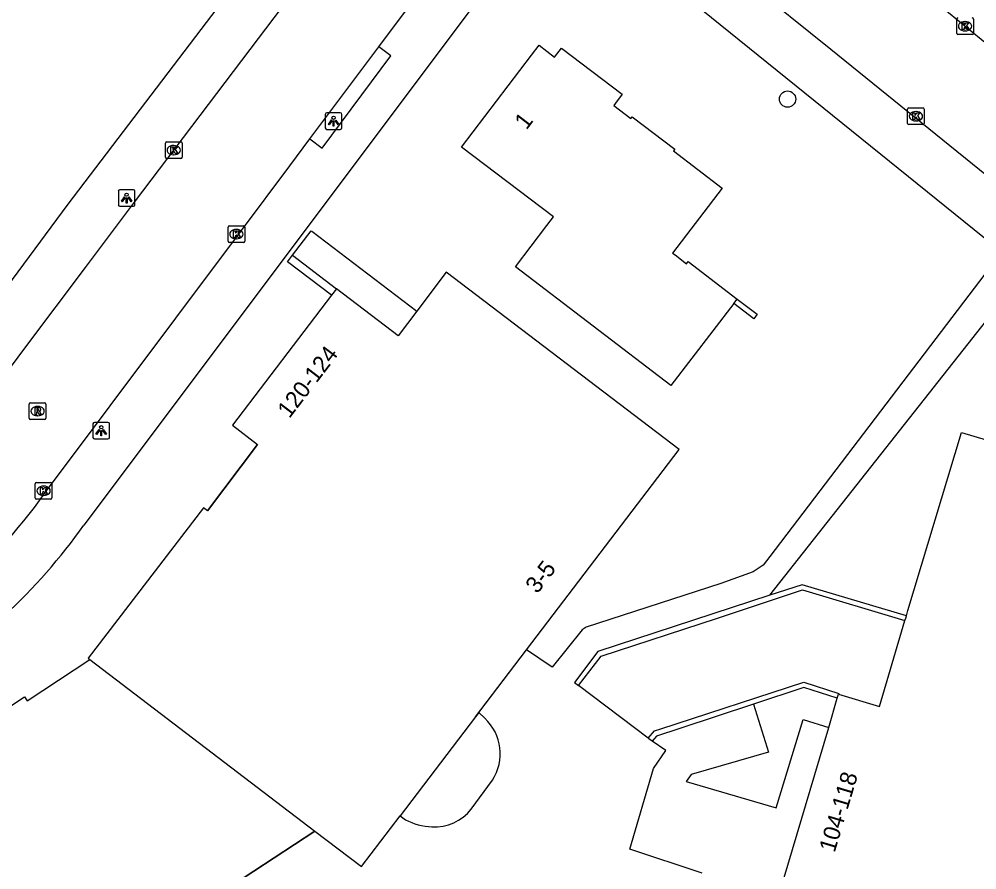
# Model space of a CAD drawing. Extents: x 161141 to 161601, y 381708 to 382245.
# Drawn here: x 161351.2 to 161408.7, y 381859.9 to 381911 of the extents above; entities that cross this region are included whole.
import ezdxf

# ---------------------------------------------------------------- set-up
doc = ezdxf.new("R2010")
doc.units = 0
for name, color, linetype in [('IMGEO_Boom', 7, 'Continuous'), ('IMGEO_Hek', 7, 'Continuous'), ('IMGEO_Kolk', 7, 'Continuous'), ('IMGEO_Lichtpunt', 7, 'Continuous'), ('IMGEO_Muur', 7, 'Continuous'), ('IMGEO_Pand', 7, 'Continuous'), ('IMGEO_Pand_nummerreeks', 7, 'Continuous'), ('IMGEO_Rijbaan_lokaal_open', 7, 'Continuous'), ('IMGEO_Rioolput', 7, 'Continuous'), ('IMGEO_Voetpad_gesloten', 7, 'Continuous'), ('IMGEO_Voetpad_op_trap', 7, 'Continuous'), ('IMGEO_Voetpad_open', 7, 'Continuous')]:
    doc.layers.add(name, color=color, linetype=linetype)

msp = doc.modelspace()

# ---------------------------------------------------------------- linework, layer by layer
at = {"layer": 'IMGEO_Boom'}
msp.add_circle((161397.349, 381906.221), 0.489, dxfattribs=at)
at = {"layer": 'IMGEO_Hek'}
for points in [[(161362.5, 381881.493), (161365.51, 381885.478)], [(161378.602, 381869.107), (161381.677, 381873.144)], [(161351.666, 381870.071), (161355.437, 381872.558)], [(161360.471, 381856.669), (161368.964, 381862.254)]]:
    msp.add_lwpolyline(points, dxfattribs=at)
at = {"layer": 'IMGEO_Kolk'}
for p, q in [((161407.513, 381910.173), (161407.513, 381911.025)), ((161408.001, 381910.879), (161408.026, 381910.879)), ((161408.514, 381911.025), (161408.514, 381910.173)), ((161408.024, 381910.319), (161407.999, 381910.319)), ((161408.44, 381910.099), (161407.588, 381910.099)), ((161404.558, 381904.763), (161404.558, 381905.615)), ((161404.633, 381905.689), (161405.485, 381905.689)), ((161405.559, 381905.615), (161405.559, 381904.763)), ((161405.046, 381905.469), (161405.071, 381905.469)), ((161405.485, 381904.689), (161404.633, 381904.689)), ((161405.069, 381904.909), (161405.044, 381904.909)), ((161359.98, 381902.729), (161359.98, 381903.581)), ((161360.055, 381903.655), (161360.907, 381903.655)), ((161360.468, 381903.435), (161360.493, 381903.435)), ((161360.981, 381903.581), (161360.981, 381902.729)), ((161360.491, 381902.875), (161360.466, 381902.875)), ((161360.907, 381902.655), (161360.055, 381902.655)), ((161363.743, 381897.685), (161363.743, 381898.537)), ((161363.818, 381898.611), (161364.67, 381898.611)), ((161364.231, 381898.391), (161364.256, 381898.391)), ((161364.744, 381898.537), (161364.744, 381897.685)), ((161364.67, 381897.611), (161363.818, 381897.611)), ((161364.254, 381897.831), (161364.229, 381897.831)), ((161352.235, 381883.192), (161353.087, 381883.192)), ((161352.16, 381882.266), (161352.16, 381883.118)), ((161352.648, 381882.972), (161352.673, 381882.972)), ((161353.161, 381883.118), (161353.161, 381882.266)), ((161353.087, 381882.192), (161352.235, 381882.192)), ((161352.671, 381882.412), (161352.646, 381882.412))]:
    msp.add_line(p, q, dxfattribs=at)
for points in [[(161407.513, 381910.173), (161407.513, 381911.025)], [(161407.834, 381910.799), (161407.957, 381910.799), (161407.957, 381910.648), (161408.087, 381910.799), (161408.251, 381910.799), (161408.105, 381910.648), (161408.258, 381910.399), (161408.106, 381910.399), (161408.021, 381910.563), (161407.957, 381910.496), (161407.957, 381910.399), (161407.834, 381910.399), (161407.834, 381910.799)], [(161408.514, 381911.025), (161408.514, 381910.173)], [(161408.44, 381910.099), (161407.588, 381910.099)], [(161404.558, 381904.763), (161404.558, 381905.615)], [(161404.633, 381905.689), (161405.485, 381905.689)], [(161405.559, 381905.615), (161405.559, 381904.763)], [(161404.879, 381905.389), (161405.002, 381905.389), (161405.002, 381905.238), (161405.132, 381905.389), (161405.296, 381905.389), (161405.15, 381905.238), (161405.303, 381904.989), (161405.151, 381904.989), (161405.066, 381905.153), (161405.002, 381905.086), (161405.002, 381904.989), (161404.879, 381904.989), (161404.879, 381905.389)], [(161405.485, 381904.689), (161404.633, 381904.689)], [(161359.98, 381902.729), (161359.98, 381903.581)], [(161360.055, 381903.655), (161360.907, 381903.655)], [(161360.301, 381903.355), (161360.424, 381903.355), (161360.424, 381903.204), (161360.554, 381903.355), (161360.718, 381903.355), (161360.572, 381903.204), (161360.725, 381902.955), (161360.573, 381902.955), (161360.488, 381903.119), (161360.424, 381903.052), (161360.424, 381902.955), (161360.301, 381902.955), (161360.301, 381903.355)], [(161360.981, 381903.581), (161360.981, 381902.729)], [(161360.907, 381902.655), (161360.055, 381902.655)], [(161363.743, 381897.685), (161363.743, 381898.537)], [(161363.818, 381898.611), (161364.67, 381898.611)], [(161364.064, 381898.311), (161364.187, 381898.311), (161364.187, 381898.16), (161364.317, 381898.311), (161364.481, 381898.311), (161364.335, 381898.16), (161364.488, 381897.911), (161364.336, 381897.911), (161364.251, 381898.075), (161364.187, 381898.008), (161364.187, 381897.911), (161364.064, 381897.911), (161364.064, 381898.311)], [(161364.744, 381898.537), (161364.744, 381897.685)], [(161364.67, 381897.611), (161363.818, 381897.611)], [(161352.235, 381883.192), (161353.087, 381883.192)], [(161352.16, 381882.266), (161352.16, 381883.118)], [(161352.481, 381882.892), (161352.604, 381882.892), (161352.604, 381882.741), (161352.734, 381882.892), (161352.898, 381882.892), (161352.752, 381882.741), (161352.905, 381882.492), (161352.753, 381882.492), (161352.668, 381882.656), (161352.604, 381882.589), (161352.604, 381882.492), (161352.481, 381882.492), (161352.481, 381882.892)], [(161353.161, 381883.118), (161353.161, 381882.266)], [(161353.087, 381882.192), (161352.235, 381882.192)]]:
    msp.add_lwpolyline(points, dxfattribs=at)
for centre, start, end in [((161407.59, 381911.023), 91.55205, 178.44795), ((161407.59, 381911.023), 91.55205, 178.44795), ((161408.438, 381911.023), 1.55205, 88.44795), ((161408.438, 381911.023), 1.55205, 88.44795), ((161407.59, 381910.175), 181.55205, 268.44795), ((161407.59, 381910.175), 181.55205, 268.44795), ((161408.438, 381910.175), 271.55205, 358.44795), ((161408.438, 381910.175), 271.55205, 358.44795), ((161404.635, 381905.613), 91.55205, 178.44795), ((161404.635, 381905.613), 91.55205, 178.44795), ((161405.483, 381905.613), 1.55205, 88.44795), ((161405.483, 381905.613), 1.55205, 88.44795), ((161404.635, 381904.765), 181.55205, 268.44795), ((161404.635, 381904.765), 181.55205, 268.44795), ((161405.483, 381904.765), 271.55205, 358.44795), ((161405.483, 381904.765), 271.55205, 358.44795), ((161360.057, 381903.579), 91.55205, 178.44795), ((161360.057, 381903.579), 91.55205, 178.44795), ((161360.905, 381903.579), 1.55205, 88.44795), ((161360.905, 381903.579), 1.55205, 88.44795), ((161360.057, 381902.731), 181.55205, 268.44795), ((161360.057, 381902.731), 181.55205, 268.44795), ((161360.905, 381902.731), 271.55205, 358.44795), ((161360.905, 381902.731), 271.55205, 358.44795), ((161363.82, 381898.535), 91.55205, 178.44795), ((161363.82, 381898.535), 91.55205, 178.44795), ((161364.668, 381898.535), 1.55205, 88.44795), ((161364.668, 381898.535), 1.55205, 88.44795), ((161363.82, 381897.687), 181.55205, 268.44795), ((161363.82, 381897.687), 181.55205, 268.44795), ((161364.668, 381897.687), 271.55205, 358.44795), ((161364.668, 381897.687), 271.55205, 358.44795), ((161352.237, 381883.116), 91.55205, 178.44795), ((161352.237, 381883.116), 91.55205, 178.44795), ((161353.085, 381883.116), 1.55205, 88.44795), ((161353.085, 381883.116), 1.55205, 88.44795), ((161352.237, 381882.268), 181.55205, 268.44795), ((161352.237, 381882.268), 181.55205, 268.44795), ((161353.085, 381882.268), 271.55205, 358.44795), ((161353.085, 381882.268), 271.55205, 358.44795)]:
    msp.add_arc(centre, 0.0765, start, end, dxfattribs=at)
for centre, major_axis, ratio, start_param, end_param in [((161408, 381910.599), (-0.387, 0.002), 0.722429, 4.712389, 7.853982), ((161408.025, 381910.599), (-0.39, 0.002), 0.717154, 1.570796, 4.712389), ((161405.045, 381905.189), (-0.387, 0.002), 0.722429, 4.712389, 7.853982), ((161405.07, 381905.189), (-0.39, 0.002), 0.717154, 1.570796, 4.712389), ((161360.467, 381903.155), (-0.387, 0.002), 0.722429, 4.712389, 7.853982), ((161360.492, 381903.155), (-0.39, 0.002), 0.717154, 1.570796, 4.712389), ((161364.23, 381898.111), (-0.387, 0.002), 0.722429, 4.712389, 7.853982), ((161364.255, 381898.111), (-0.39, 0.002), 0.717154, 1.570796, 4.712389), ((161352.647, 381882.692), (-0.387, 0.002), 0.722429, 4.712389, 7.853982), ((161352.672, 381882.692), (-0.39, 0.002), 0.717154, 1.570796, 4.712389)]:
    msp.add_ellipse(centre, major_axis=major_axis, ratio=ratio, start_param=start_param, end_param=end_param, dxfattribs=at)
at = {"layer": 'IMGEO_Lichtpunt'}
for p, q in [((161369.583, 381905.303), (161369.583, 381904.496)), ((161369.583, 381905.303), (161369.583, 381904.496)), ((161370.485, 381905.398), (161369.677, 381905.398)), ((161370.485, 381905.398), (161369.677, 381905.398)), ((161370.579, 381904.496), (161370.579, 381905.303)), ((161370.579, 381904.496), (161370.579, 381905.303)), ((161369.677, 381904.402), (161370.485, 381904.402)), ((161369.677, 381904.402), (161370.485, 381904.402)), ((161357.152, 381900.683), (161357.152, 381899.876)), ((161357.152, 381900.683), (161357.152, 381899.876)), ((161358.054, 381900.778), (161357.246, 381900.778)), ((161358.054, 381900.778), (161357.246, 381900.778)), ((161358.148, 381899.876), (161358.148, 381900.683)), ((161358.148, 381899.876), (161358.148, 381900.683)), ((161357.246, 381899.782), (161358.054, 381899.782)), ((161357.246, 381899.782), (161358.054, 381899.782)), ((161355.623, 381886.707), (161355.623, 381885.9)), ((161355.623, 381886.707), (161355.623, 381885.9)), ((161356.525, 381886.802), (161355.717, 381886.802)), ((161356.525, 381886.802), (161355.717, 381886.802)), ((161356.619, 381885.9), (161356.619, 381886.707)), ((161356.619, 381885.9), (161356.619, 381886.707)), ((161355.717, 381885.806), (161356.525, 381885.806)), ((161355.717, 381885.806), (161356.525, 381885.806))]:
    msp.add_line(p, q, dxfattribs=at)
for points in [[(161369.957, 381904.967), (161369.996, 381904.939), (161369.808, 381904.677), (161369.77, 381904.704), (161369.957, 381904.967)], [(161370.059, 381904.919), (161370.106, 381904.919), (161370.106, 381904.597), (161370.059, 381904.597), (161370.059, 381904.919)], [(161370.169, 381904.939), (161370.207, 381904.966), (161370.394, 381904.704), (161370.355, 381904.676), (161370.169, 381904.939)], [(161357.526, 381900.347), (161357.565, 381900.319), (161357.377, 381900.057), (161357.339, 381900.084), (161357.526, 381900.347)], [(161357.628, 381900.299), (161357.675, 381900.299), (161357.675, 381899.977), (161357.628, 381899.977), (161357.628, 381900.299)], [(161357.738, 381900.319), (161357.776, 381900.346), (161357.963, 381900.084), (161357.924, 381900.056), (161357.738, 381900.319)], [(161355.997, 381886.371), (161356.036, 381886.343), (161355.848, 381886.081), (161355.81, 381886.108), (161355.997, 381886.371)], [(161356.099, 381886.323), (161356.146, 381886.323), (161356.146, 381886.001), (161356.099, 381886.001), (161356.099, 381886.323)], [(161356.209, 381886.343), (161356.247, 381886.37), (161356.434, 381886.108), (161356.395, 381886.08), (161356.209, 381886.343)]]:
    msp.add_lwpolyline(points, dxfattribs=at)
for centre in [(161370.082, 381905.101), (161357.651, 381900.481), (161356.122, 381886.505)]:
    msp.add_circle(centre, 0.0994, dxfattribs=at)
for centre, start, end in [((161369.677, 381905.303), 90, 180), ((161369.677, 381905.303), 90, 180), ((161370.485, 381905.303), 0, 90), ((161370.485, 381905.303), 0, 90), ((161369.677, 381904.496), 180, 270), ((161369.677, 381904.496), 180, 270), ((161370.485, 381904.496), 270, 0), ((161370.485, 381904.496), 270, 360), ((161357.246, 381900.683), 90, 180), ((161357.246, 381900.683), 90, 180), ((161358.054, 381900.683), 0, 90), ((161358.054, 381900.683), 0, 90), ((161357.246, 381899.876), 180, 270), ((161357.246, 381899.876), 180, 270), ((161358.054, 381899.876), 270, 0), ((161358.054, 381899.876), 270, 360), ((161355.717, 381886.707), 90, 180), ((161355.717, 381886.707), 90, 180), ((161356.525, 381886.707), 0, 90), ((161356.525, 381886.707), 0, 90), ((161355.717, 381885.9), 180, 270), ((161355.717, 381885.9), 180, 270), ((161356.525, 381885.9), 270, 0), ((161356.525, 381885.9), 270, 360)]:
    msp.add_arc(centre, 0.0946, start, end, dxfattribs=at)
at = {"layer": 'IMGEO_Muur'}
for points in [[(161369.955, 381894.435), (161367.312, 381896.447), (161367.614, 381896.841)], [(161367.614, 381896.841), (161370.262, 381894.819)], [(161394.333, 381894.213), (161395.529, 381893.303), (161395.317, 381893.025), (161394.124, 381893.943)], [(161404.489, 381875.181), (161398.229, 381877.051), (161396.286, 381876.416)], [(161396.286, 381876.416), (161385.946, 381873.035), (161384.544, 381871.18), (161384.784, 381871)], [(161384.784, 381871), (161386.159, 381872.748), (161393.152, 381875.047), (161398.239, 381876.735), (161404.403, 381874.894)], [(161388.983, 381867.825), (161389.367, 381868.28), (161389.733, 381868.393), (161398.335, 381871.191), (161400.422, 381870.513), (161400.411, 381870.476)], [(161400.337, 381870.225), (161398.337, 381870.875), (161395.311, 381869.871)], [(161395.311, 381869.871), (161390.886, 381868.403), (161389.475, 381867.942), (161389.223, 381867.644)], [(161389.223, 381867.644), (161389.02, 381867.798), (161388.983, 381867.825)]]:
    msp.add_lwpolyline(points, dxfattribs=at)
at = {"layer": 'IMGEO_Pand'}
for points in [[(161394.124, 381893.943), (161390.337, 381889.021), (161381.005, 381896.145), (161382.897, 381898.632), (161383.285, 381899.142), (161377.771, 381903.34), (161381.969, 381908.853), (161382.429, 381909.459), (161383.354, 381908.75), (161383.765, 381909.292), (161387.42, 381906.518), (161387.018, 381905.98), (161386.918, 381905.847), (161387.94, 381905.066), (161388.016, 381905.165), (161390.578, 381903.207), (161390.502, 381903.108), (161393.417, 381900.88), (161390.444, 381896.971), (161390.591, 381896.859), (161391.284, 381896.332), (161391.385, 381896.466), (161394.333, 381894.213)], [(161381.677, 381873.144), (161390.838, 381885.171), (161376.851, 381895.819), (161375.084, 381893.489)], [(161370.262, 381894.819), (161369.955, 381894.435)], [(161375.084, 381893.489), (161373.955, 381892.001), (161370.262, 381894.819)], [(161369.955, 381894.435), (161364, 381886.63), (161365.51, 381885.478), (161362.5, 381881.493), (161362.266, 381881.673), (161355.333, 381872.637), (161355.437, 381872.558)], [(161394.124, 381893.943), (161394.333, 381894.213)], [(161404.489, 381875.181), (161404.584, 381875.499), (161407.805, 381886.188), (161423.433, 381881.545), (161420.059, 381870.284)], [(161404.403, 381874.894), (161404.449, 381875.049), (161404.489, 381875.181)], [(161400.411, 381870.476), (161402.871, 381869.734), (161404.403, 381874.894)], [(161378.802, 381869.369), (161381.677, 381873.144)], [(161345.758, 381855.638), (161342.849, 381853.685), (161337.847, 381861.294), (161342.013, 381864.045), (161351.507, 381870.313), (161351.666, 381870.071), (161355.437, 381872.558)], [(161355.437, 381872.558), (161368.964, 381862.254)], [(161399.821, 381868.48), (161400.337, 381870.225)], [(161400.337, 381870.225), (161400.411, 381870.476)], [(161378.802, 381869.369), (161378.602, 381869.107), (161374.079, 381863.168)], [(161396.815, 381858.319), (161399.821, 381868.48)], [(161368.964, 381862.254), (161371.759, 381860.122), (161374.079, 381863.168)], [(161368.964, 381862.254), (161360.411, 381856.63)]]:
    msp.add_lwpolyline(points, dxfattribs=at)
at = {"layer": 'IMGEO_Rijbaan_lokaal_open'}
for points in [[(161430.53, 381892.26), (161428.93, 381893.541), (161416.582, 381903.762), (161409.42, 381909.443), (161405.146, 381912.95), (161401.483, 381915.955), (161397.742, 381918.904), (161394.58, 381921.397), (161388.533, 381926.301), (161384.971, 381929.006), (161381.728, 381931.469), (161381.315, 381931.756), (161376.383, 381935.18), (161370.251, 381939.135), (161367.432, 381940.939), (161364.318, 381942.933), (161361.946, 381944.451), (161354.44, 381949.434), (161345.5, 381955.194), (161345.132, 381955.433), (161341.968, 381957.49), (161334.965, 381962.043), (161325.373, 381968.263), (161318.237, 381972.89)], [(161347.78, 381886.211), (161351.589, 381891.33), (161355.178, 381896.112), (161357.581, 381899.312), (161358.116, 381900.025), (161368.51, 381913.776), (161373.481, 381920.434), (161374.759, 381922.138), (161375.72, 381923.419)], [(161426.69, 381887.564), (161425.057, 381888.885), (161404.152, 381905.797), (161399.947, 381909.192), (161394.957, 381913.221), (161391.403, 381916.091), (161386.448, 381920.091)], [(161372.8, 381909.362), (161380.355, 381919.457)], [(161368.658, 381903.827), (161372.8, 381909.362)], [(161352.722, 381882.533), (161364.546, 381898.333), (161367.452, 381902.216), (161368.658, 381903.827)], [(161410.212, 381897.05), (161396.293, 381878.738), (161395.877, 381878.224), (161395.275, 381877.818), (161393.345, 381877.126), (161385.244, 381874.499), (161385.019, 381874.335), (161383.219, 381872.094), (161381.677, 381873.144)], [(161396.286, 381876.416), (161411.648, 381895.891)], [(161388.983, 381867.825), (161384.784, 381871)], [(161379.167, 381869.023), (161378.802, 381869.369)], [(161392.214, 381859.719), (161387.882, 381861.165), (161389.294, 381866.012), (161390.047, 381867.09), (161389.223, 381867.644)], [(161378.344, 381863.568), (161379.62, 381865.312)], [(161374.079, 381863.168), (161374.394, 381862.928)]]:
    msp.add_lwpolyline(points, dxfattribs=at)
for centre, radius, start, end in [((161325.528, 381901.818), 33.338, 296.19299, 324.65779), ((161377.177, 381866.897), 2.912, 327.02435, 46.89492), ((161376.187, 381865.229), 2.722, 265.88663, 322.39046), ((161376.08, 381866.145), 3.632, 242.34105, 268.60995)]:
    msp.add_arc(centre, radius, start, end, dxfattribs=at)
at = {"layer": 'IMGEO_Rioolput'}
for p, q in [((161351.799, 381887.053), (161351.799, 381887.905)), ((161351.874, 381887.979), (161352.726, 381887.979)), ((161352.8, 381887.905), (161352.8, 381887.053)), ((161352.31, 381887.199), (161352.285, 381887.199)), ((161352.287, 381887.759), (161352.312, 381887.759)), ((161352.726, 381886.979), (161351.874, 381886.979))]:
    msp.add_line(p, q, dxfattribs=at)
for points in [[(161351.799, 381887.053), (161351.799, 381887.905)], [(161351.874, 381887.979), (161352.726, 381887.979)], [(161352.8, 381887.905), (161352.8, 381887.053)], [(161352.388, 381887.677), (161352.136, 381887.679), (161352.136, 381887.279)], [(161352.136, 381887.279), (161352.26, 381887.279), (161352.26, 381887.441), (161352.271, 381887.441)], [(161352.314, 381887.598), (161352.26, 381887.598), (161352.26, 381887.517)], [(161352.26, 381887.517), (161352.312, 381887.517)], [(161352.318, 381887.412), (161352.389, 381887.279), (161352.529, 381887.279), (161352.464, 381887.405)], [(161352.726, 381886.979), (161351.874, 381886.979)]]:
    msp.add_lwpolyline(points, dxfattribs=at)
for centre, radius, start, end in [((161351.876, 381887.903), 0.0765, 91.55205, 178.44795), ((161351.876, 381887.903), 0.0765, 91.55205, 178.44795), ((161352.724, 381887.903), 0.0765, 1.55205, 88.44795), ((161352.724, 381887.903), 0.0765, 1.55205, 88.44795), ((161352.27, 381887.388), 0.0533, 26.02933, 88.69889), ((161352.296, 381887.706), 0.19, 274.7715, 282.96867), ((161352.32, 381887.502), 0.0964, 77.00612, 93.18647), ((161352.334, 381887.559), 0.0378, 276.66336, 79.67722), ((161352.387, 381887.567), 0.109, 350.36119, 89.41601), ((161352.385, 381887.567), 0.112, 277.58423, 350.98172), ((161352.369, 381887.352), 0.108, 29.51342, 73.79051), ((161351.876, 381887.055), 0.0765, 181.55205, 268.44795), ((161351.876, 381887.055), 0.0765, 181.55205, 268.44795), ((161352.724, 381887.055), 0.0765, 271.55205, 358.44795), ((161352.724, 381887.055), 0.0765, 271.55205, 358.44795)]:
    msp.add_arc(centre, radius, start, end, dxfattribs=at)
for centre, major_axis, ratio, start_param, end_param in [((161352.286, 381887.479), (-0.387, 0.002), 0.722429, 4.712389, 7.853982), ((161352.311, 381887.479), (-0.39, 0.002), 0.717154, 1.570796, 4.712389)]:
    msp.add_ellipse(centre, major_axis=major_axis, ratio=ratio, start_param=start_param, end_param=end_param, dxfattribs=at)
at = {"layer": 'IMGEO_Voetpad_gesloten'}
msp.add_lwpolyline([(161395.311, 381869.871), (161396.198, 381866.981), (161391.555, 381865.65), (161391.264, 381865.226), (161396.671, 381863.647), (161398.279, 381868.954), (161399.821, 381868.48)], dxfattribs=at)
at = {"layer": 'IMGEO_Voetpad_op_trap'}
msp.add_lwpolyline([(161367.614, 381896.841), (161368.743, 381898.317), (161368.776, 381898.292), (161375.084, 381893.489)], dxfattribs=at)
at = {"layer": 'IMGEO_Voetpad_open'}
for points in [[(161342.481, 381884.773), (161344.76, 381887.264), (161354.145, 381899.917), (161371.073, 381922.177), (161372.043, 381923.95)], [(161382.438, 381917.119), (161355.077, 381880.626)], [(161384.753, 381917.612), (161384.887, 381917.504), (161410.212, 381897.05)], [(161368.658, 381903.827), (161369.388, 381903.281), (161373.53, 381908.815), (161372.8, 381909.362)]]:
    msp.add_lwpolyline(points, dxfattribs=at)
msp.add_arc((161326.096, 381901.218), 35.552, 301.32262, 324.6045, dxfattribs=at)

# ---------------------------------------------------------------- texts
at = {"layer": 'IMGEO_Pand_nummerreeks'}
for s, rotation, p in [('1', 52.51158, (161381.668, 381904.333)), ('120-124', 52.65482, (161367.426, 381886.999)), ('3-5', 52.70066, (161382.32, 381876.464)), ('104-118', 73.32141, (161400.178, 381860.917))]:
    msp.add_text(s, height=1, rotation=rotation, dxfattribs=at).set_placement(p)

doc.saveas('drawing.dxf')
